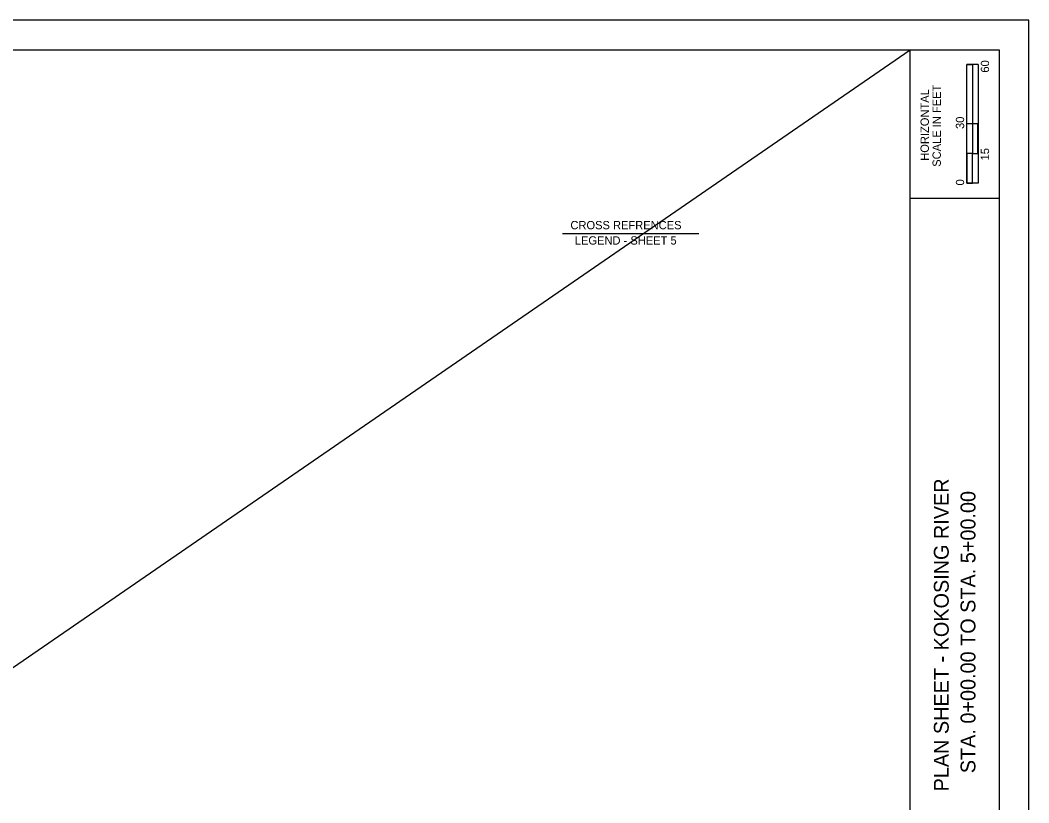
# Model space of a CAD drawing. Extents: x 0 to 34, y -1.8 to 22.
# Drawn here: x 17 to 34, y 8.81 to 22 of the extents above; entities that cross this region are included whole.
import ezdxf

# ---------------------------------------------------------------- set-up
doc = ezdxf.new("R2010")
doc.units = 0
for name, color, linetype in [('CS-ALGN-TEXT', 7, 'Continuous'), ('CS-ANNO', 7, 'Continuous'), ('CS-ANNO-MATC', 7, 'Continuous'), ('CS-PROF-TEXT', 7, 'Continuous'), ('CS-PROP-BNDY', 7, 'Continuous')]:
    doc.layers.add(name, color=color, linetype=linetype)

msp = doc.modelspace()

# ---------------------------------------------------------------- linework, layer by layer
at = {"layer": 'CS-ALGN-TEXT'}
msp.add_lwpolyline([(0, 0), (34, 0), (34, 22), (0, 22)], close=True, dxfattribs=at)
at = {"layer": 'CS-ANNO'}
for p, q in [((32, 0.5), (32, 21.5)), ((32, 19), (33.5, 19))]:
    msp.add_line(p, q, dxfattribs=at)
msp.add_lwpolyline([(1.5, 21.5), (33.5, 21.5), (33.5, 0.5), (1.5, 0.5)], close=True, dxfattribs=at)
at = {"layer": 'CS-ANNO-MATC'}
for p, q in [((32.957, 19.25), (32.957, 21.25)), ((33.144, 21.25), (32.957, 21.25)), ((32.957, 20.25), (32.957, 21.25)), ((32.957, 21.25), (33.05, 21.25)), ((33.05, 21.25), (33.051, 21.25)), ((33.051, 21.25), (33.051, 20.25)), ((33.144, 21.25), (33.144, 19.25)), ((33.051, 20.25), (32.957, 20.25)), ((33.143, 20.25), (33.05, 20.25)), ((33.05, 20.25), (33.05, 19.75)), ((33.143, 19.75), (33.143, 20.25)), ((33.05, 19.75), (32.957, 19.75)), ((32.957, 19.75), (32.957, 19.25)), ((33.05, 19.25), (33.05, 19.75)), ((33.05, 19.75), (33.143, 19.75)), ((33.144, 19.25), (32.957, 19.25)), ((32.957, 19.25), (33.05, 19.25)), ((26.141, 18.406), (28.441, 18.406))]:
    msp.add_line(p, q, dxfattribs=at)
at = {"layer": 'CS-PROF-TEXT'}
msp.add_line((1.5, 0.5), (32, 21.5), dxfattribs=at)

# ---------------------------------------------------------------- texts
at = {"layer": 'CS-ANNO-MATC'}
for s, height, p in [('60', 0.14, (33.33, 21.116)), ('HORIZONTAL', 0.14, (32.315, 19.63)), ('SCALE IN FEET', 0.14, (32.517, 19.529)), ('30', 0.14, (32.91, 20.166)), ('15', 0.14, (33.33, 19.636)), ('0', 0.14, (32.91, 19.214)), ('PLAN SHEET - KOKOSING RIVER', 0.25, (32.65, 8.999)), ('STA. 0+00.00 TO STA. 5+00.00', 0.25, (33.1, 9.306))]:
    msp.add_text(s, height=height, rotation=90, dxfattribs=at).set_placement(p)
at = {"layer": 'CS-PROP-BNDY'}
for s, p in [('CROSS REFRENCES', (26.274, 18.475)), ('LEGEND - SHEET 5', (26.348, 18.217))]:
    msp.add_text(s, height=0.14, rotation=360, dxfattribs=at).set_placement(p)

doc.saveas('drawing.dxf')
